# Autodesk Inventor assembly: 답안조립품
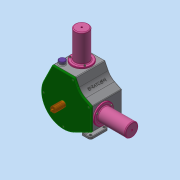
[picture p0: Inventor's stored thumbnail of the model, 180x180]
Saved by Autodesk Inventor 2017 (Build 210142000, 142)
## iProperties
Part Number: 답안조립품
Material: 일반
Document SubType Name: Assembly
Designer: MRC
Author: MRC
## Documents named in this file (13)
- C:\Users\MRC\Desktop\611109V1007\답안조립품.iam
- C:\Users\MRC\Desktop\611109V1007\너트 M3.ipt
- C:\Users\MRC\Desktop\611109V1007\베어링 20 x 37 x 9.ipt
- C:\Users\MRC\Desktop\611109V1007\본체.ipt
- C:\Users\MRC\Desktop\611109V1007\볼트 M3 x 12.ipt
- C:\Users\MRC\Desktop\611109V1007\실린더.ipt
- C:\Users\MRC\Desktop\611109V1007\앞커버.ipt
- C:\Users\MRC\Desktop\611109V1007\축.ipt
- C:\Users\MRC\Desktop\611109V1007\측정게이지.ipt
- C:\Users\MRC\Desktop\611109V1007\커넥팅로드 캡.ipt
- C:\Users\MRC\Desktop\611109V1007\커넥팅로드.ipt
- C:\Users\MRC\Desktop\611109V1007\피스톤 핀.ipt
- C:\Users\MRC\Desktop\611109V1007\피스톤.ipt
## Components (4 placed, 2 different names)
1. 피스톤 핀:1
2. 피스톤:1
3. 피스톤 핀:2
4. 피스톤:2
